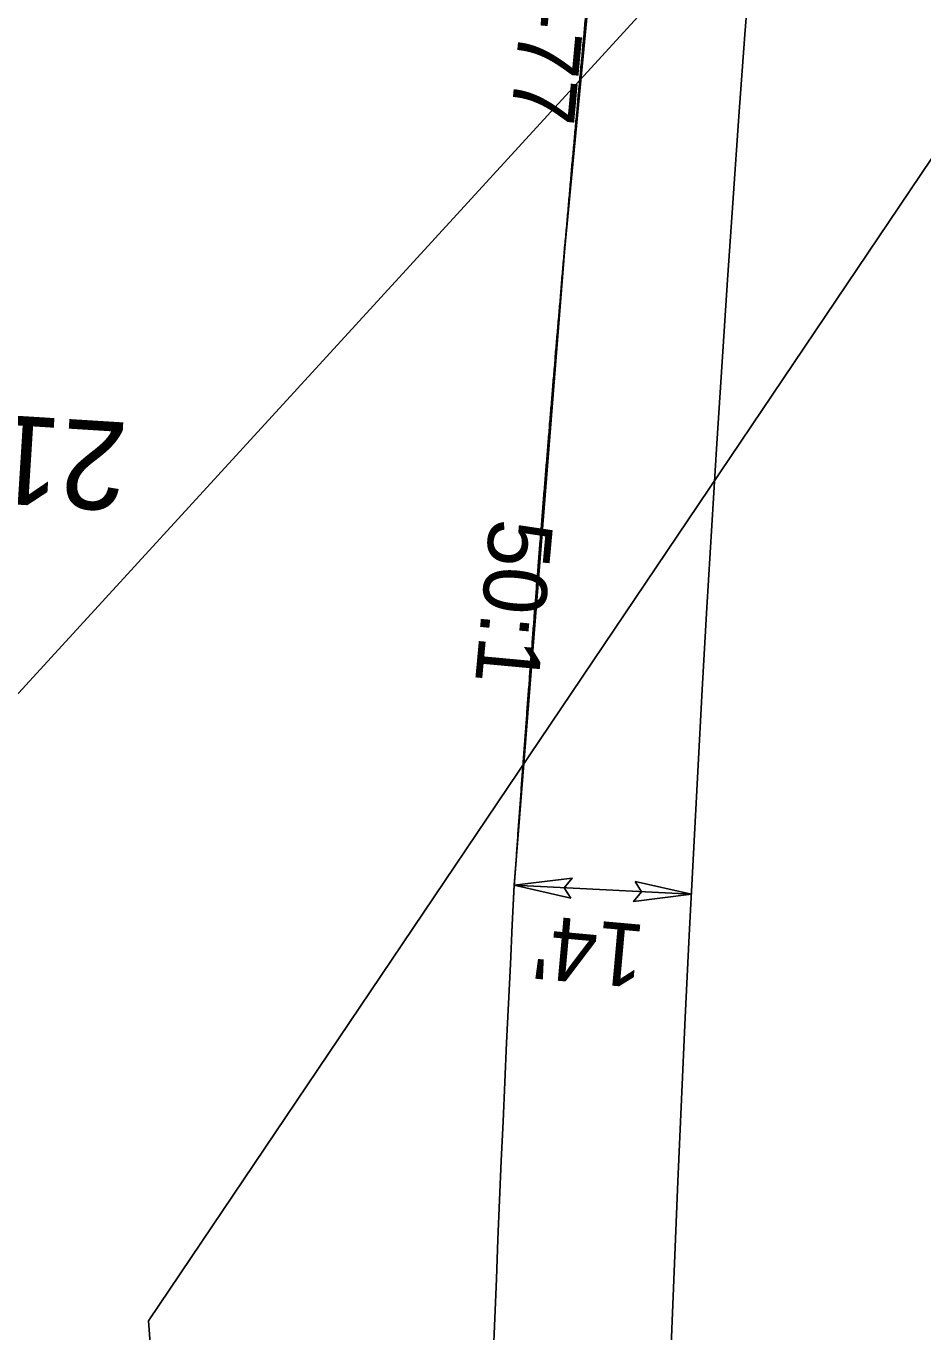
# Model space of a CAD drawing. Extents: x 2389694 to 2405615, y 546931 to 573532.
# Drawn here: x 2400056 to 2400126.8, y 568149.3 to 568252.4 of the extents above; entities that cross this region are included whole.
import ezdxf

# ---------------------------------------------------------------- set-up
doc = ezdxf.new("R2010")
doc.units = 0
for name, color, linetype in [('Prop Dimension', 7, 'Continuous'), ('Prop Dimension Text', 7, 'Continuous'), ('Prop EOT', 7, 'Continuous'), ('Prop Guardrail', 7, 'Continuous'), ('Prop Horizontal Alignment Curve and Spiral Data', 7, 'Continuous')]:
    doc.layers.add(name, color=color, linetype=linetype)

msp = doc.modelspace()

# ---------------------------------------------------------------- linework, layer by layer
at = {"layer": 'Prop Dimension'}
for p, q in [((2400165.83, 568320.38), (2400033.57, 568175.96)), ((2400163.47, 568295.43), (2400065.62, 568150.18)), ((2400094.51, 568184.56), (2400108.49, 568183.85)), ((2400065.62, 568150.18), (2400071.73, 568064.47))]:
    msp.add_line(p, q, dxfattribs=at)
for points in [[(2400098.96, 568183.55), (2400094.51, 568184.56), (2400099.07, 568185.13), (2400098.45, 568184.36)], [(2400104.04, 568184.85), (2400108.49, 568183.85), (2400103.93, 568183.28), (2400104.55, 568184.05)]]:
    msp.add_lwpolyline(points, close=True, dxfattribs=at)
at = {"layer": 'Prop EOT'}
for radius, start in [(2947, 148.75529), (2961, 177.09437)]:
    msp.add_arc((2403051.7, 568034.46), radius, start, 180.94658, dxfattribs=at)
for points in [[(2400098.53, 568235.45), (2400098.6, 568236.14), (2400098.66, 568236.82), (2400098.72, 568237.51), (2400098.78, 568238.2), (2400098.84, 568238.89), (2400098.9, 568239.57), (2400098.96, 568240.26), (2400099.02, 568240.95), (2400099.08, 568241.63), (2400099.15, 568242.32), (2400099.21, 568243), (2400099.27, 568243.7), (2400099.33, 568244.38), (2400099.39, 568245.07), (2400099.46, 568245.76), (2400099.52, 568246.44), (2400099.58, 568247.13), (2400099.65, 568247.81), (2400099.71, 568248.5), (2400099.77, 568249.19), (2400099.84, 568249.88), (2400099.9, 568250.56), (2400099.96, 568251.25), (2400100.03, 568251.94), (2400100.09, 568252.62), (2400100.16, 568253.31), (2400100.22, 568253.99), (2400100.29, 568254.68), (2400100.35, 568255.36), (2400100.42, 568256.06), (2400100.48, 568256.75), (2400100.55, 568257.43), (2400100.61, 568258.12), (2400100.68, 568258.8), (2400100.74, 568259.49), (2400100.81, 568260.17), (2400100.88, 568260.86), (2400100.94, 568261.55), (2400101.01, 568262.23), (2400101.08, 568262.92), (2400101.14, 568263.6), (2400101.21, 568264.3), (2400101.28, 568264.98), (2400101.34, 568265.67), (2400101.41, 568266.36), (2400101.48, 568267.04), (2400101.55, 568267.73), (2400101.61, 568268.41), (2400101.68, 568269.1), (2400101.75, 568269.78), (2400101.82, 568270.47), (2400101.89, 568271.16), (2400101.96, 568271.84), (2400102.02, 568272.53), (2400102.09, 568273.21), (2400102.16, 568273.9), (2400102.23, 568274.58), (2400102.3, 568275.27), (2400102.37, 568275.95), (2400102.44, 568276.65), (2400102.51, 568277.34), (2400102.58, 568278.02), (2400102.65, 568278.71), (2400102.72, 568279.39), (2400102.79, 568280.08), (2400102.86, 568280.76), (2400102.93, 568281.45), (2400103.01, 568282.14), (2400103.08, 568282.82), (2400103.15, 568283.51), (2400103.22, 568284.19), (2400103.29, 568284.88), (2400103.44, 568286.25)], [(2400094.51, 568184.56), (2400094.56, 568185.25), (2400094.61, 568185.93), (2400094.66, 568186.62), (2400094.7, 568187.31), (2400094.75, 568188), (2400094.8, 568188.68), (2400094.85, 568189.37), (2400094.9, 568190.07), (2400094.95, 568190.75), (2400095, 568191.44), (2400095.05, 568192.12), (2400095.1, 568192.82), (2400095.15, 568193.5), (2400095.2, 568194.19), (2400095.25, 568194.88), (2400095.31, 568195.57), (2400095.36, 568196.26), (2400095.41, 568196.94), (2400095.46, 568197.63), (2400095.51, 568198.32), (2400095.56, 568199.01), (2400095.61, 568199.69), (2400095.67, 568200.38), (2400095.72, 568201.08), (2400095.77, 568201.76), (2400095.82, 568202.45), (2400095.88, 568203.13), (2400095.93, 568203.82), (2400095.98, 568204.51), (2400096.04, 568205.2), (2400096.09, 568205.89), (2400096.14, 568206.57), (2400096.2, 568207.27), (2400096.25, 568207.95), (2400096.3, 568208.64), (2400096.36, 568209.32), (2400096.41, 568210.01), (2400096.47, 568210.71), (2400096.52, 568211.39), (2400096.58, 568212.08), (2400096.63, 568212.76), (2400096.69, 568213.45), (2400096.74, 568214.14), (2400096.8, 568214.83), (2400096.85, 568215.52), (2400096.91, 568216.2), (2400096.96, 568216.89), (2400097.02, 568217.58), (2400097.08, 568218.27), (2400097.13, 568218.95), (2400097.19, 568219.64), (2400097.25, 568220.33), (2400097.3, 568221.02), (2400097.36, 568221.71), (2400097.42, 568222.39), (2400097.48, 568223.08), (2400097.53, 568223.76), (2400097.59, 568224.45), (2400097.65, 568225.14), (2400097.71, 568225.83), (2400097.76, 568226.52), (2400097.82, 568227.2), (2400097.88, 568227.89), (2400097.94, 568228.57), (2400098, 568229.27), (2400098.06, 568229.95), (2400098.12, 568230.64), (2400098.18, 568231.33), (2400098.23, 568232.01), (2400098.29, 568232.7), (2400098.35, 568233.39), (2400098.41, 568234.08), (2400098.47, 568234.76), (2400098.53, 568235.45)]]:
    msp.add_spline(points, degree=3, dxfattribs=at)
at = {"layer": 'Prop Guardrail'}
for p, q in [((2400103.44, 568286.25), (2400098.49, 568234.9)), ((2400098.49, 568234.9), (2400094.51, 568184.56))]:
    msp.add_line(p, q, dxfattribs=at)
msp.add_arc((2403051.7, 568034.46), 2961, 177.09434, 180.94654, dxfattribs=at)

# ---------------------------------------------------------------- texts
at = {"layer": 'Prop Dimension Text'}
for s, rotation, p in [('TYPE B-77', 264.7043, (2400097.31, 568278.21)), ('50:1', 264.7043, (2400092.61, 568213.61)), ("14'", 174.8377, (2400104.96, 568181.41))]:
    msp.add_text(s, height=5, rotation=rotation, dxfattribs=at).set_placement(p)
at = {"layer": 'Prop Horizontal Alignment Curve and Spiral Data'}
msp.add_text('210', height=7, rotation=176.4153, dxfattribs=at).set_placement((2400064.1, 568221.08))

doc.saveas('drawing.dxf')
